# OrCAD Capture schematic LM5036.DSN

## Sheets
1 PAGE1: size Custom; title: LM5036 Half Bridge Controller; rev: 1.0; note: SNVSB14A
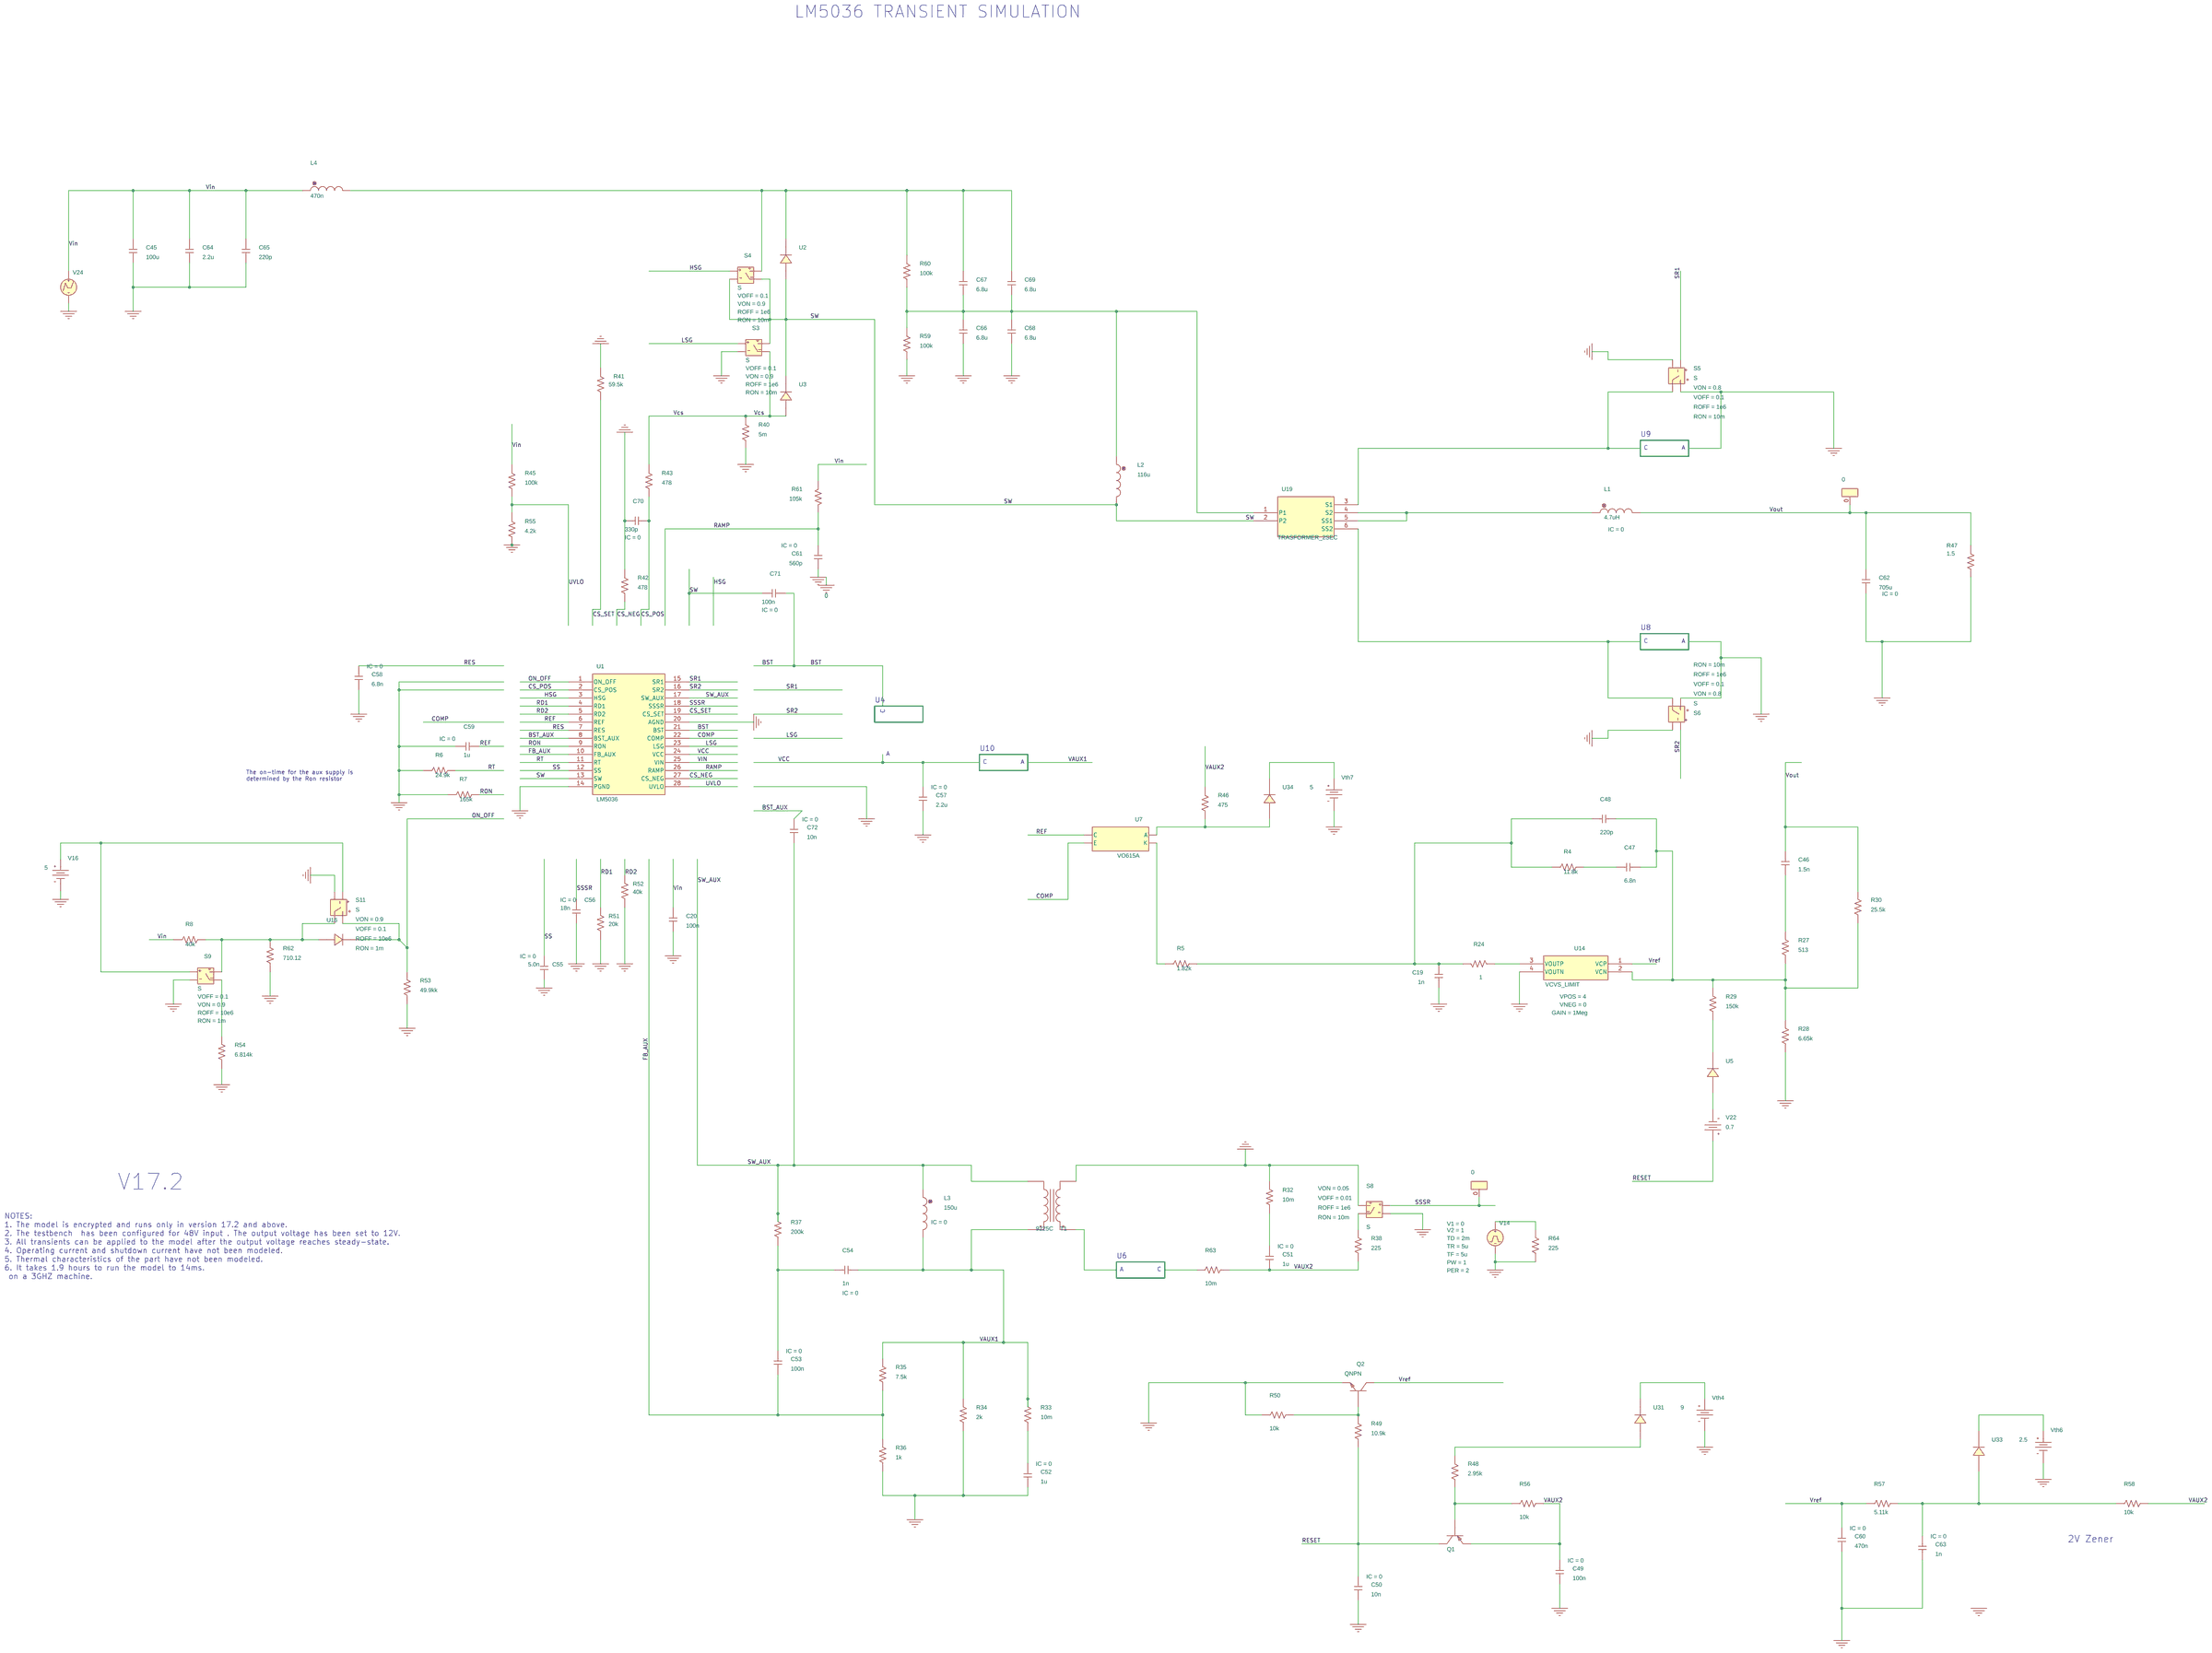
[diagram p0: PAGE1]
2 PAGE1 (2): size A; block U10
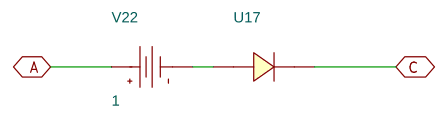
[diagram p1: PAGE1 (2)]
3 PAGE1 (3): block U8, another copy of sheet 2
4 PAGE1 (4): block U9, another copy of sheet 2
5 PAGE1 (5): block U6, another copy of sheet 2
6 PAGE1 (6): block U4, another copy of sheet 2

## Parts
sheet PAGE1 (2)
V22#2  VDC
sheet PAGE1 (3)
U17#2  D_D1
V22#3  VDC
sheet PAGE1 (4)
U17#3  D_D1
V22#4  VDC
sheet PAGE1 (5)
U17#4  D_D1
V22#5  VDC
sheet PAGE1 (6)
U17  D_D1
U17#5  D_D1
V22  VDC
V22#6  VDC
sheet PAGE1
C19  1n  [RAD/CK05]
C20  100n  [RAD/CK05]
C45  100u  [RAD/CK05]
C46  1.5n  [RAD/CK05]
C47  6.8n  [RAD/CK05]
C48  220p  [RAD/CK05]
C49  100n  [RAD/CK05]
C50  10n  [RAD/CK05]
C51  1u  [RAD/CK05]
C52  1u  [RAD/CK05]
C53  100n  [RAD/CK05]
C54  1n  [RAD/CK05]
C55  5.0n  [RAD/CK05]
C56  18n  [RAD/CK05]
C57  2.2u  [RAD/CK05]
C58  6.8n  [RAD/CK05]
C59  1u  [RAD/CK05]
C60  470n  [RAD/CK05]
C61  560p  [RAD/CK05]
C62  705u  [RAD/CK05]
C63  1n  [RAD/CK05]
C64  2.2u  [RAD/CK05]
C65  220p  [RAD/CK05]
C66  6.8u  [RAD/CK05]
C67  6.8u  [RAD/CK05]
C68  6.8u  [RAD/CK05]
C69  6.8u  [RAD/CK05]
C70  330p  [RAD/CK05]
C71  100n  [RAD/CK05]
C72  10n  [RAD/CK05]
IC6  0
IC8  0
L1  4.7uH  [DISC/.350x.175/LS.200x.100/.034]
L2  116u  [DISC/.350x.175/LS.200x.100/.034]
L3  150u  [DISC/.350x.175/LS.200x.100/.034]
L4  470n  [DISC/.350x.175/LS.200x.100/.034]
Q1  Q_Q1
Q2  QNPN
R4  11.8k  [AX/RC05]
R5  1.82k  [AX/RC05]
R6  24.9k  [AX/RC05]
R7  165k  [AX/RC05]
R8  40k  [AX/RC05]
R24  1  [AX/RC05]
R27  513  [AX/RC05]
R28  6.65k  [AX/RC05]
R29  150k  [AX/RC05]
R30  25.5k  [AX/RC05]
R32  10m  [AX/RC05]
R33  10m  [AX/RC05]
R34  2k  [AX/RC05]
R35  7.5k  [AX/RC05]
R36  1k  [AX/RC05]
R37  200k  [AX/RC05]
R38  225  [AX/RC05]
R40  5m  [AX/RC05]
R41  59.5k  [AX/RC05]
R42  478  [AX/RC05]
R43  478  [AX/RC05]
R45  100k  [AX/RC05]
R46  475  [AX/RC05]
R47  1.5  [AX/RC05]
R48  2.95k  [AX/RC05]
R49  10.9k  [AX/RC05]
R50  10k  [AX/RC05]
R51  20k  [AX/RC05]
R52  40k  [AX/RC05]
R53  49.9kk  [AX/RC05]
R54  6.814k  [AX/RC05]
R55  4.2k  [AX/RC05]
R56  10k  [AX/RC05]
R57  5.11k  [AX/RC05]
R58  10k  [AX/RC05]
R59  100k  [AX/RC05]
R60  100k  [AX/RC05]
R61  105k  [AX/RC05]
R62  710.12  [AX/RC05]
R63  10m  [AX/RC05]
R64  225  [AX/RC05]
S3  S
S4  S
S5  S
S6  S
S8  S
S9  S
S11  S
T1  9225C
U1  LM5036
U2  D_D1
U3  D_D1
U5  D_D1
U7  VO615A
U14  VCVS_LIMIT
U16  D_D1
U19  TRASFORMER_2SEC
U31  D_D1
U33  D_D1
U34  D_D1
V14  VPULSE
V16  VDC
V24  VPWL
Vth4  VDC
Vth6  VDC
Vth7  VDC

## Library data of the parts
V22 V22#2-V22#6 = VDC: DC: 1
U2 U3 U5 U16 U17 U17#2-U17#5 U31 U33 U34 = D_D1
C19 C20 C45-C48 C64-C69 = C
C49-C63 C70-C72 = C: IC: 0
IC6 IC8 = IC1
L1 L3 = L: IC: 0
L2 L4 = L
Q1 = Q_Q1
Q2 = 2N2222
R4-R8 R24 R27-R30 R32-R38 R40-R43 R45-R64 = R
S3 S4 = S: ROFF: 1e6; RON: 10m; VOFF: 0.1; VON: 0.9
S5 S6 = S: ROFF: 1e6; RON: 10m; VOFF: 0.1; VON: 0.8
S8 = S: ROFF: 1e6; RON: 10m; VOFF: 0.01; VON: 0.05
S9 S11 = S: ROFF: 10e6; RON: 1m; VOFF: 0.1; VON: 0.9
T1 = 9225C
U1 = LM5036
U7 = VO615A
U14 = VCVS_LIMIT_0: GAIN: 1Meg; VNEG: 0; VPOS: 4
U19 = TRASFORMER_1
V14 = VPULSE: PER: 2; PW: 1; TD: 2m; TF: 5u; TR: 5u; V1: 0; V2: 1
V16 Vth7 = VDC: DC: 5
V24 = VPWL: T1: 0; T2: 100u; V1: 48; V2: 48
Vth4 = VDC: DC: 9
Vth6 = VDC: DC: 2.5

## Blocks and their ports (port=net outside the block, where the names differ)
U10 = schematic 1VDiode, on sheet PAGE1: A=VAUX1, C=VCC
U8 = schematic 1VDiode, on sheet PAGE1: A=0, C=N128430
U9 = schematic 1VDiode, on sheet PAGE1: A=0, C=N127834
U6 = schematic 1VDiode, on sheet PAGE1: A=N131064, C=N131296
U4 = schematic 1VDiode, on sheet PAGE1: A=VCC, C=BST

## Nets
VCC: C57.1 U1.24(VCC) U17.2 V22#6.0(+)
VIN: C20.1 C45.1 C64.1 C65.1 L4.1 R8.1 R45.1 R61.1 U1.25(VIN) V24.1(+)
0: C19.1 C20.2 C45.2 C49.2 C50.2 C52.2 C55.2 C56.2 C57.2 C58.2 C59.2 C60.2 C61.2 C62.2 C63.2 C64.2 C65.2 C66.2 C68.2 C70.1 Q2.1(E) R6.1 R7.1 R28.1 R32.2 R34.1 R36.1 R40.2 R41.1 R42.1 R47.2 R50.1 R51.1 R52.1 R53.1 R54.1 R55.2 R59.2 R62.1 R64.1 S3.1(2) S5.1(2) S5.2(3) S6.1(2) S6.2(3) S8.1(2) S8.2(3) S9.1(2) S11.1(2) T1.4 U1.14(PGND) U1.20(AGND) U14.4(VOUTN) V14.2(-) V16.1(-) V22#3.0(+) V22#4.0(+) V24.2(-) Vth4.1(-) Vth6.1(-) Vth7.1(-)
BST: C71.2 U1.21(BST) U17#5.2
BST_AUX: C72.1 U1.8(BST_AUX)
COMP: U1.22(COMP) U7.E
CS_NEG: R42.2 U1.27(CS_NEG)
CS_POS: C70.2 R43.2 U1.2(CS_POS)
CS_SET: R41.2 U1.19(CS_SET)
FB_AUX: C53.2 R35.1 R36.2 U1.10(FB_AUX)
HSG: S4.0(1) U1.3(HSG)
LSG: S3.0(1) U1.23(LSG)
ON_OFF: R53.2 S11.2(3) U1.1(ON_OFF) U16.2
RAMP: C61.1 R61.2 U1.26(RAMP)
RD1: R51.2 U1.4(RD1)
RD2: R52.2 U1.5(RD2)
REF: C59.1 U1.6(REF) U7.C
RES: C58.1 U1.7(RES)
RESET: C50.1 Q1.3(C) R49.2 V22.0(+)
RON: R7.2 U1.9(RON)
RT: R6.2 U1.11(RT)
SR1: S5.0(1) U1.15(SR1)
SR2: S6.0(1) U1.16(SR2)
SS: C55.1 U1.12(SS)
SSSR: C56.1 IC8.0(+) S8.0(1) U1.18(SSSR)
SW: C71.1 L2.2 S3.2(3) S4.1(2) S4.3(4) U1.13(SW) U2.1 U3.2 U19.2(P2)
SW_AUX: C72.2 L3.1 R37.2 T1.2 U1.17(SW_AUX)
UVLO: R45.2 R55.1 U1.28(UVLO)
VAUX1: C54.2 L3.2 R33.2 R34.2 R35.2 T1.1 V22#2.0(+)
VAUX2: C49.1 C51.2 Q1.1(E) R38.1 R46.1 R56.2 R58.2 R63.1
Vcs: R40.1 R43.1 S3.3(4) U3.1
Vout: C46.1 C62.1 IC6.0(+) L1.2 R30.2 R47.1
Vref: C60.1 Q2.3(C) R57.1 U14.1(VCP)
N127134: C67.1 C69.1 L4.2 R60.1 S4.2(3) U2.2
N127436: C66.1 C67.2 C68.1 C69.2 L2.1 R59.1 R60.2 U19.1(P1)
N127834: S5.3(4) U17#3.2 U19.3(S1)
N128250: L1.1 U19.4(S2) U19.5(SS1)
N128430: S6.3(4) U17#2.2 U19.6(SS2)
N129142: U34.2 Vth7.0(+)
N129396: R46.2 U7.A U34.1
N129404: C19.2 C48.2 R4.1 R5.2 R24.2
N129414: C47.1 C48.1 R27.1 R28.2 R29.2 R30.1 U14.2(VCN)
N129522: S9.0(1) S11.0(1) V16.0(+)
N129564: R5.1 U7.K
N129744: C47.2 R4.2
N129784: C46.2 R27.2
N130030: R8.2 R62.2 S9.2(3) S11.3(4) U16.1
N130416: R24.1 U14.3(VOUTP)
N130484: R54.2 S9.3(4)
N130620: R29.1 U5.2
N130720: U5.1 V22.1(-)
N131002: C51.1 R32.1
N131008: R38.2 S8.3(4)
N131046: R64.2 V14.1(+)
N131064: T1.3 V22#5.0(+)
N131174: C53.1 C54.1 R37.1
N131296: R63.2 U17#4.2
N131464: C52.1 R33.1
N131568: U31.2 Vth4.0(+)
N131654: Q2.2(B) R49.1 R50.2
N131690: U33.2 Vth6.0(+)
N131774: R48.1 U31.1
N131854: C63.1 R57.2 R58.1 U33.1
N131866: Q1.2(B) R48.2 R56.1
U4/N16699319: U17#5.1 V22#6.1(-)
U6/N16699319: U17#4.1 V22#5.1(-)
U8/N16699319: U17#2.1 V22#3.1(-)
U9/N16699319: U17#3.1 V22#4.1(-)
U10/N16699319: U17.1 V22#2.1(-)

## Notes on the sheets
sheet 1
- LM5036 TRANSIENT SIMULATION
- The on-time for the aux supply is
  determined by the Ron resistor
- V17.2
- NOTES:
  1. The model is encrypted and runs only in version 17.2 and above.
  2. The testbench  has been configured for 48V input . The output voltage has been set to 12V.
  3. All transients can be applied to the model after the output voltage reaches steady-state.
  4. Operating current and shutdown current have not been modeled.
  5. Thermal characteristics of the part have not been modeled.
  6. It takes 1.9 hours to run the model to 14ms.
   on a 3GHZ machine.
- 2V Zener
